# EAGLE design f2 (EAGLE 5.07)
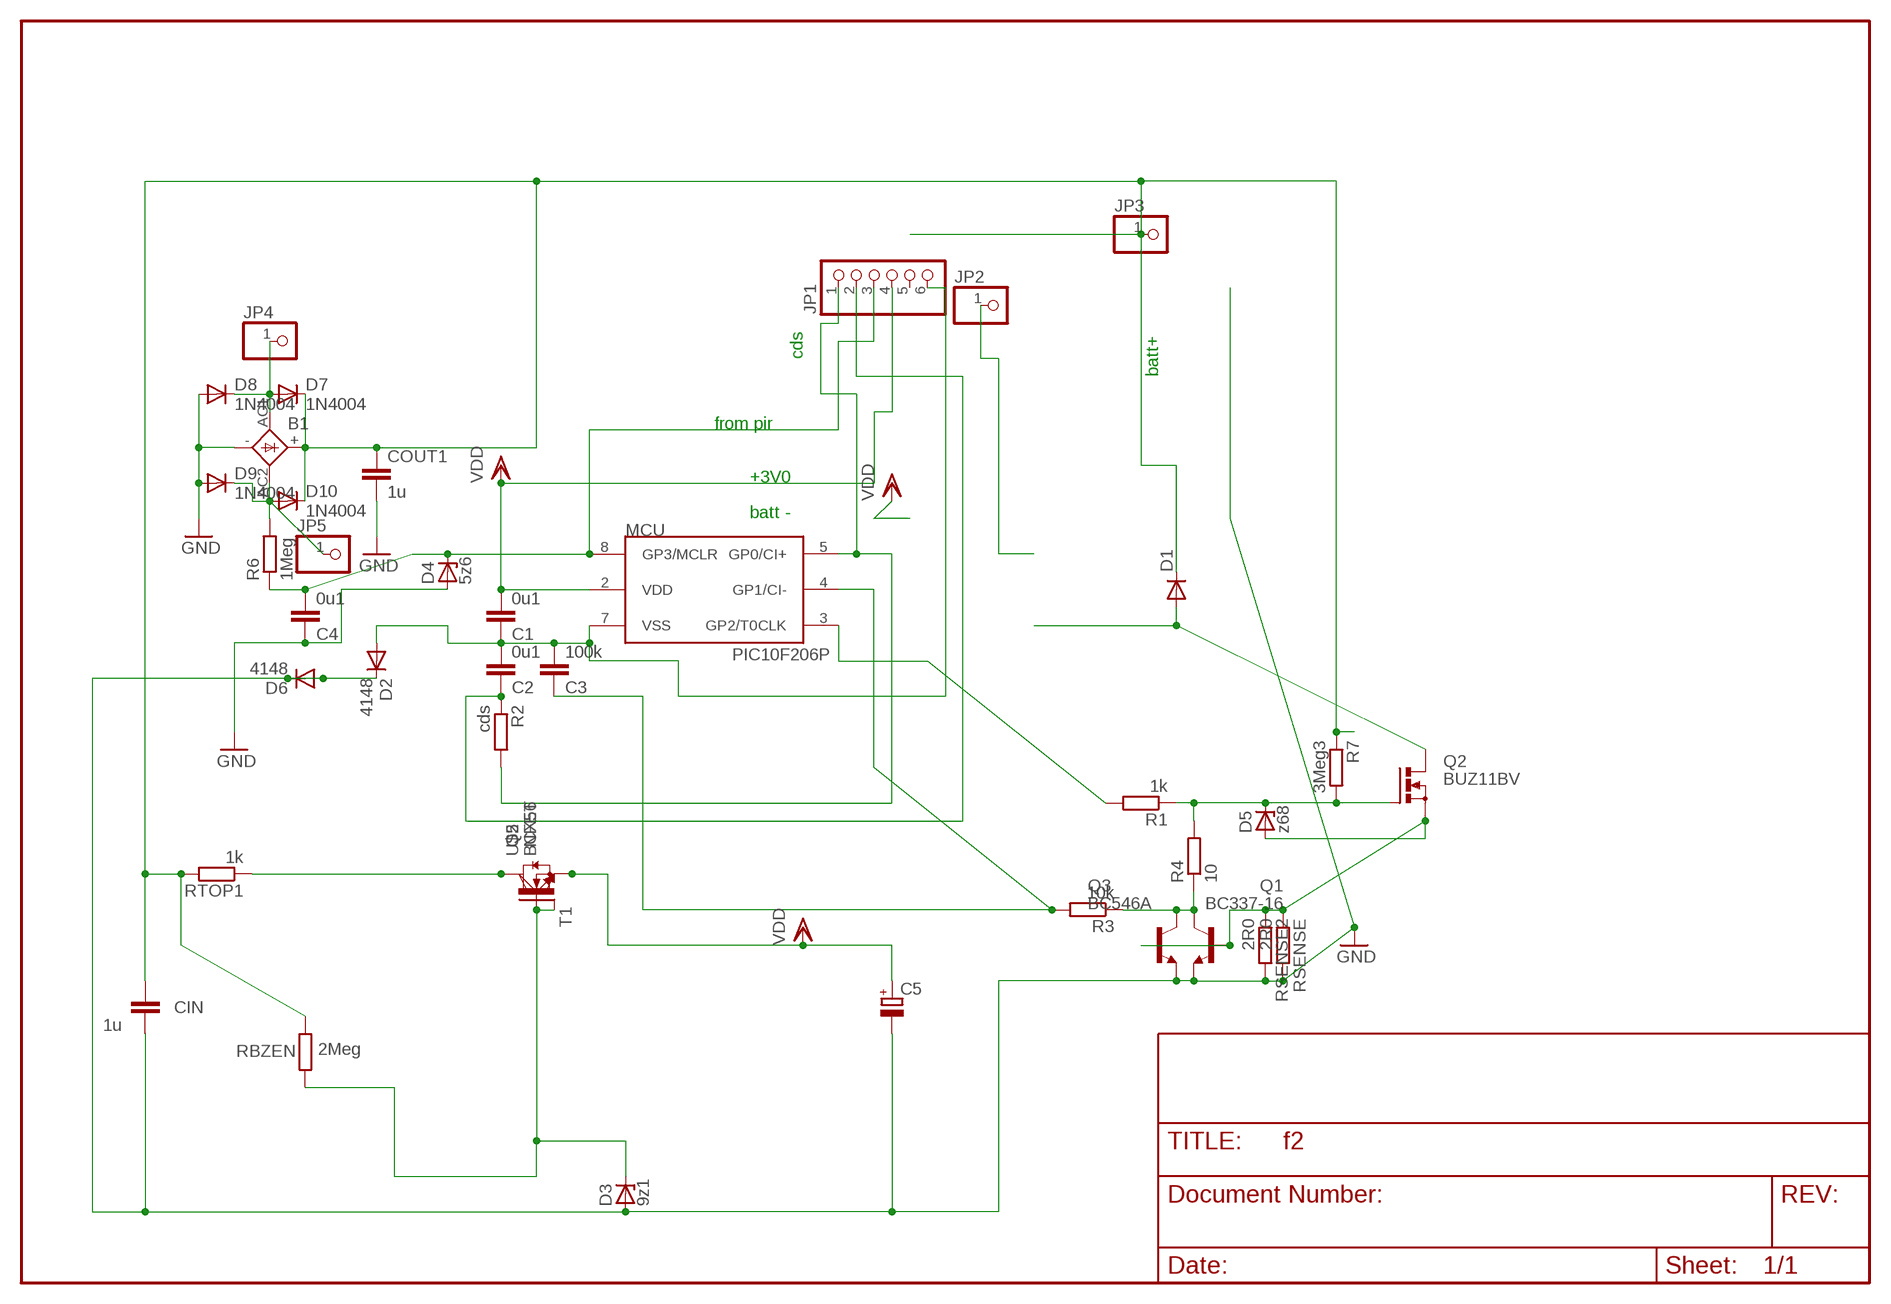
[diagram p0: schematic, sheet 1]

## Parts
B1  1KAB  [1KAB]
C1  0u1  C-EUC1206  [C1206]
C2  0u1  C-EUC0805  [C0805]
C3  100k  C-EUC1206  [C1206]
C4  0u1  C-EUC1206  [C1206]
C5  CPOL-EUSANYO_SMD_C6  [SANYO-OSCON_SMD_C6]
CIN  1u  C-EU050-024X044  [C050-024X044]
COUT1  1u  C-EU075-032X103  [C075-032X103]
D1  DIODE-SMC  [SMC]
D2  4148  1N4148MINIMELF  [MINIMELF]
D3  9z1  ZENER-DIODESOD80C  [SOD80C]
D4  5z6  ZENER-DIODESOD80C  [SOD80C]
D5  z68  ZENER-DIODEZD-5  [ZDIO-5]
D6  4148  1N4148MINIMELF  [MINIMELF]
D7  1N4004  [D-3.75]
D8  1N4004  [D-3.75]
D9  1N4004  [D-3.75]
D10  1N4004  [D-3.75]
JP1  PINHD-1X6  [1X06BOX]
JP2  PINHD-1X11X0.4  [1X01]
JP3  PINHD-1X11X0.4  [1X01]
JP4  PINHD-1X11X0.4  [1X01]
JP5  PINHD-1X11X0.4  [1X01]
MCU  PIC10F206P  [DIL8]
Q1  BC337-16  [TO92]
Q2  BUZ11BV  [TO220BV]
Q3  BC546A  [TO92-EBC]
Q5  NFET  N-HEXFET_DPAK-  [TO252]
R1  1k  R-EU_R0805  [R0805]
R2  cds  R-EU_0204/2V  [0204V]
R3  10k  R-EU_R1206  [R1206]
R4  10  R-EU_0207/3V  [0207/3V]
R6  1Meg  R-EU_0207/30  [0207/30]
R7  3Meg3  R-EU_0207/3V  [0207/3V]
RBZEN  2Meg  R-EU_0204/7  [0204/7]
RSENSE  2R0  R-EU_0207/3V  [0207/3V]
RSENSE2  2R0  R-EU_0207/3V  [0207/3V]
RTOP1  1k  R-EU_R1206  [R1206]
T1  -NPN-TO126V  [TO126V]
U$2  BCX56  [SOT223]

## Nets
AC1: B1.AC1 D7.A D8.C JP4.1
AC2: B1.AC2 D9.C D10.A JP5.1 R6.2
BN: D5.A Q1.2(B) Q2.S Q3.B RSENSE2.1 RSENSE.1
C: Q5.3(D) RTOP1.1 T1.2(C) U$2.2(C)
CB: D3.C Q5.1(G) RBZEN.2 T1.3(B) U$2.1(B)
CN: Q1.3(C) Q3.C R3.1 R4.1
GATE: D5.C Q2.G R1.1 R4.2 R7.2
GND: B1.- C4.1 C5.- CIN.2 COUT1.2 D2.C D3.A D4.A D6.A D6.C D8.A D9.A Q1.1(E) Q3.E RSENSE2.2 RSENSE.2
HOT: D1.A Q2.D
LED-: JP2.1
N$2: JP1.1 MCU.5(GP0/CI+) R2.2
N$4: C3.1 MCU.4(GP1/CI-) R3.2
N$6: C4.2 D4.C JP1.3 MCU.8(GP3/MCLR) R6.1
N$11: C2.1 JP1.2 R2.1
N$14: MCU.3(GP2/T0CLK) R1.2
VDD: C1.2 C5.+ JP1.4 MCU.2(VDD) Q5.2(S) T1.1(E) U$2.3(E)
VPLUS: B1.+ CIN.1 COUT1.1 D1.C D7.C D10.C JP3.1 R7.1 RBZEN.1 RTOP1.2
VSS: C1.1 C2.2 C3.2 D2.A JP1.6 MCU.7(VSS)
Unconnected: JP1.5

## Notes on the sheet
- cds
- batt+
- from pir
- +3V0
- batt -

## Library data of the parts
B1 = rectifier:1KAB: RECTIFIER grid 5,08 x 5,08 mm
C1-C4 CIN COUT1 = rcl:C-EU: CAPACITOR, European symbol
C5 = rcl-2:CPOL-EU: POLARIZED CAPACITOR, European symbol
D1 = diode-1:DIODE-: DIODE
D2 D6 = diode-1:1N4148: DIODE
D3-D5 = diode:ZENER-DIODE: Z-Diode
D7-D10 = diode:1N4004: DIODE
JP1 = pinhead:PINHD-1X6: PIN HEADER
JP2-JP5 = pinhead:PINHD-1X1: PIN HEADER
MCU = microchip-3:PIC10F2*: uPC nW 0,25/0,5k Program Flash memory Comparator
Q1 = transistor-npn:BC337*: NPN Transistor
Q2 = transistor-power:BUZ11: N-CHANNEL MOS FET
Q3 = transistor-npn:BC546*: NPN Transistor
Q5 = transistor-power:N-HEXFET_?-*: HEXFET® Power MOSFET
R1-R4 R7 RBZEN RSENSE RSENSE2 RTOP1 = rcl:R-EU_: RESISTOR, European symbol
R6 = rcl-2:R-EU_: RESISTOR, European symbol
T1 = transistor:*-NPN-: NPN Transistror BF959 corrected 2008.03.06
U$2 = transistor-power:BCX56

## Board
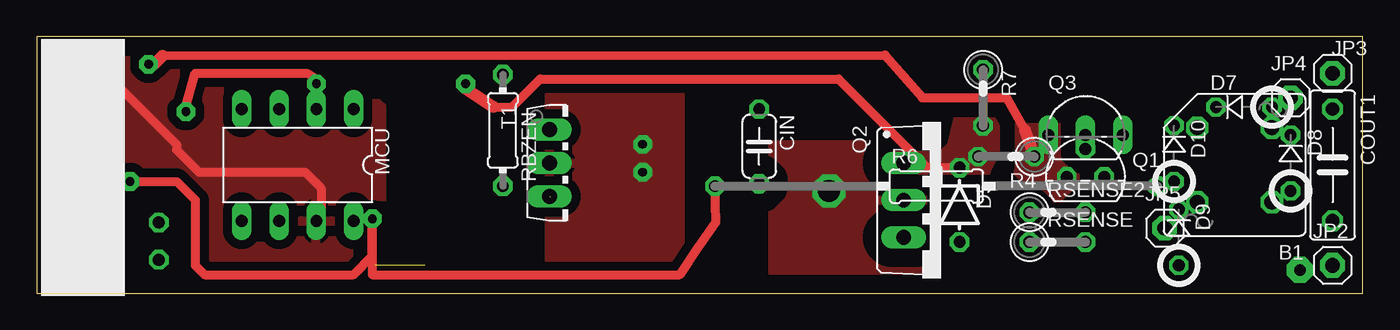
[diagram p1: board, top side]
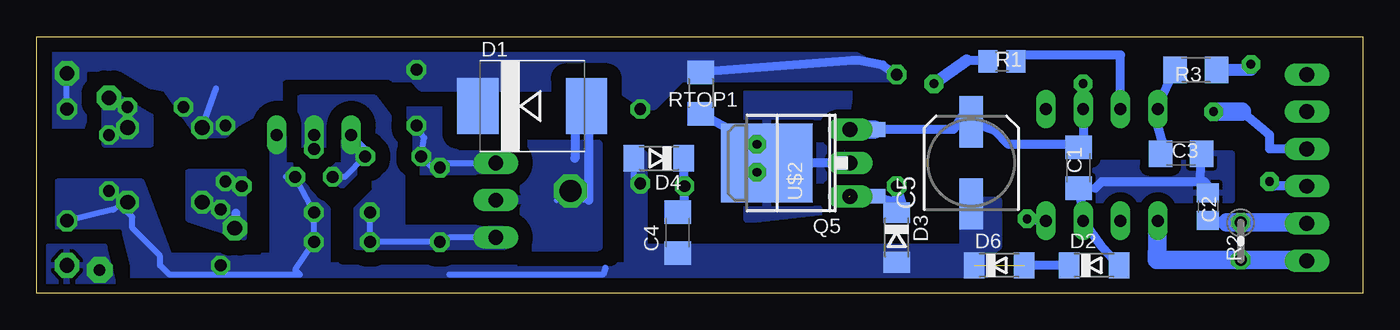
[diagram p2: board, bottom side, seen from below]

Size 90.33 x 17.5 mm. Coordinates in mm from the lower left corner, seen from the top.
Outline: 0,0 90.33,0 90.33,17.5 0,17.5 0,0
Copper layers (1*16): Top 0.035mm / dielectric 1.5mm / Bottom 0.035mm
Design rules "default *": minimum track width 10mil, minimum drill 24mil, track to track 8mil, track to pad 8mil, pad to pad 8mil, via to via 8mil, smd to smd 8mil, copper to edge 20mil, drill to drill 8mil, minimum pad ring 10mil, minimum via ring 8mil, stop-mask expansion 4mil, vias tented up to drill 0mil, thermal gap 10mil

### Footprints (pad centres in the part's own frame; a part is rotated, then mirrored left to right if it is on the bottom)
1KAB = drill 1.016 octagon: + 2.54,-2.54; - -2.54,2.54; AC1 -2.54,-2.54; AC2 2.54,2.54
C1206 = smd 1.6 x 1.8: 1 -1.4,0; 2 1.4,0
C0805 = smd 1.3 x 1.5: 1 -0.95,0; 2 0.95,0
SANYO-OSCON_SMD_C6 = smd 3.5 x 1.6: + 2.8,0; - -2.8,0
C050-024X044 = drill 0.813 octagon: 1 -2.54,0; 2 2.54,0
C075-032X103 = drill 0.914 octagon: 1 -3.81,0; 2 3.81,0
SMC = smd 2.8 x 3.8: A 3.7,0; C -3.7,0
MINIMELF = smd 1.4 x 1.8: A 1.7,0; C -1.7,0
SOD80C = smd 1.4 x 1.8: A 1.7,0; C -1.7,0
ZDIO-5 = drill 0.813 octagon: A 2.54,0; C -2.54,0
D-3.75 = drill 0.8 octagon: A 2.54,0; C -1.27,0
1X06BOX = drill 1.016 long: 1 -6.35,0; 2 -3.81,0; 3 -1.27,0; 4 1.27,0; 5 3.81,0; 6 6.35,0
1X01 = drill 1 pad 1.676 octagon: 1 0,0
DIL8 = drill 0.813 long: 1 -3.81,-3.81; 2 -1.27,-3.81; 3 1.27,-3.81; 4 3.81,-3.81; 5 3.81,3.81; 6 1.27,3.81; 7 -1.27,3.81; 8 -3.81,3.81
TO92 = drill 0.813 octagon: 1 1.27,0; 2 0,1.905; 3 -1.27,0
TO220BV = drill 1.016 long: D 0,-2.54; G -2.54,-2.54; S 2.54,-2.54
TO92-EBC = drill 0.813 long: B 0,-1.27; C -2.54,-1.27; E 2.54,-1.27
TO252 = smd 1 x 1.6: 1 -2.28,-3.53; 2 2.28,-3.53 | smd 5.4 x 6.2: 3 0,3.77
R0805 = smd 1.3 x 1.5: 1 -0.95,0; 2 0.95,0
0204V = drill 0.813 octagon: 1 -1.27,0; 2 1.27,0
R1206 = smd 1.6 x 1.803: 1 -1.422,0; 2 1.422,0
0207/3V = drill 0.813 octagon: 1 -1.27,0; 2 2.54,0
0207/30 = drill 0.813 octagon: 1 -15.08,0; 2 15.08,0
0204/7 = drill 0.813 octagon: 1 -3.81,0; 2 3.81,0
TO126V = drill 1.016 long: 1 -2.286,-1.27; 2 0,-1.27; 3 2.286,-1.27
SOT223 = smd 1.219 x 2.235: 1 -2.311,-3.099; 2 0,-3.099; 3 2.311,-3.099 | smd 3.6 x 2.2: 4 0,3.099

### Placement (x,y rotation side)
B1  81.6,8.75 180 top
C1  19.37,8.57 90 bottom
C2  10.54,5.91 90 bottom
C3  12.38,9.53 0 bottom
C4  46.67,4.13 90 bottom
C5  26.67,8.89 90 bottom
CIN  49.21,10.02 270 top
COUT1  88.27,8.75 270 top
D1  56.58,12.76 0 bottom
D2  18.3,1.91 0 bottom
D3  31.75,3.81 270 bottom
D4  47.94,9.21 180 bottom
D5  62.87,6.03 270 top
D6  24.77,1.91 0 bottom
D7  81.6,12.7 0 top
D8  85.41,9.53 270 top
D9  77.79,4.45 270 top
D10  77.47,10.16 270 top
JP1  3.81,8.57 90 top
JP2  88.27,1.91 0 top
JP3  88.27,15 0 top
JP4  85.41,13.34 0 top
JP5  76.83,4.45 0 top
MCU  17.78,8.75 180 top
Q1  71.44,7.94 0 top
Q2  61.59,6.35 270 top
Q3  71.44,12.06 0 top
Q5  36.83,8.89 90 bottom
R1  24.57,15.81 0 bottom
R2  8.32,3.56 270 bottom
R3  11.37,15.24 180 bottom
R4  66.67,9.32 180 top
R6  61.28,7.3 0 top
R7  64.45,13.97 270 top
RBZEN  31.75,11.11 270 top
RSENSE  68.9,3.49 0 top
RSENSE2  68.9,5.53 0 top
RTOP1  45.09,13.65 90 bottom
T1  36.2,8.89 270 top
U$2  38.1,8.89 90 bottom

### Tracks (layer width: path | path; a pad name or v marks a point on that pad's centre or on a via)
AC1
  Bottom 0.406: D8.C B1.AC1
  pour Bottom (isolate 0.61, no thermals): 82.55,12.06 85.72,13.97 85.72,10.16 82.55,10.16
AC2
  Bottom 0.406: R6.2 D10.A
  Bottom 0.61: JP5.1 76.75,5.48
  pour Bottom (isolate 0.813, rank 2, no thermals): 76.2,3.81 76.2,8.26 80.01,8.26 80.01,5.08
BN
  Bottom 0.406: Q2.S 62.23,3.81 D5.A RSENSE.1 RSENSE2.1
  pour Bottom (isolate 1.016, no thermals): 58.42,4.45 65.41,4.45 65.41,10.79 67.31,13.34 72.39,13.34 72.39,10.16 67.31,10.16 67.31,6.99 68.58,5.71 68.58,3.17 58.42,3.17
C  (via drill 0.6 pad 1.27)
  Bottom 0.406: T1.2 U$2.2 | v41.27,10.16 40.64,10.16 40.64,9.53
  Bottom 0.61: 40.01,8.89 40.64,9.53 | U$2.2 39.37,8.89 | 39.37,8.89 40.01,8.89 | RTOP1.1 43.33,11.28 42.55,9.53 39.37,8.89 | 40.01,8.89 Q5.3
  other vias: 41.27,8.26
  pour Bottom (isolate 0.61, rank 5): 34.92,13.97 41.91,13.97 41.91,5.08 36.2,5.71
  pour Top (isolate 0.61, rank 4): 34.92,13.97 43.81,13.97 43.81,1.91 34.92,1.91
CB  (1 unrouted)
  Bottom 0.61: D3.C RBZEN.2 31.39,6.07 Q5.1 34.29,6.61
  Bottom 1.27: 34.29,6.61 T1.3
CN  (via drill 0.6 pad 1.27)
  Top 0.61: 67.31,11.11 66.04,13.34 60.33,13.34 57.78,16.25 8.57,16.19 | v7.62,15.62 8,15.62
  Top 0.813: 8,15.62 8.57,16.19 | 67.31,11.11 R4.1
  Bottom 0.406: Q1.3 69.33,7.94 R4.1 67.94,9.84 Q3.C
  Bottom 0.61: 7.62,15.24 v7.62,15.62
  Bottom 0.813: R3.1 7.62,15.24
  pour Bottom (isolate 1.016, rank 5, no thermals): 68.58,11.43 69.85,11.43 69.85,9.53 71.12,8.26 71.12,7.62 69.85,6.35 68.58,6.35 66.67,8.26 66.67,11.43
  pour Top (isolate 1.016, rank 5, no thermals): 68.58,11.43 69.85,11.43 69.85,9.53 71.12,8.26 71.12,7.62 69.85,6.35 68.58,6.35 66.67,8.26 66.67,11.43
GATE  (via drill 0.6 pad 1.27)
  Top 0.61: v29.21,14.29 29.21,13.97 | 31.11,12.7 32.38,12.7 34.29,14.61 54.61,14.61 60.64,8.57 D5.C
  Top 0.813: 29.21,13.97 31.11,12.7
  Bottom 0.406: R7.2 63.94,10.6 R4.2 63.38,8.57 D5.C 62.55,8.89 Q2.G
  Bottom 0.61: 26.99,15.88 26.22,15.88 R1.1
  Bottom 0.813: 26.99,15.88 v29.21,14.29
  pour Bottom (isolate 1.016, rank 4, no thermals): 62.87,12.7 65.41,12.7 66.04,12.06 66.04,9.53 64.77,8.26 58.42,8.26 58.42,9.53 61.59,9.53 62.23,10.16
  pour Top (isolate 1.016, rank 4, no thermals): 62.87,12.7 65.41,12.7 65.41,9.53 64.77,8.26 58.42,8.26 58.42,9.53 61.59,9.53 62.23,10.16
GND  (1 unrouted)
  Bottom 0.406: COUT1.2 85.09,5.71 84.59,5.97 | 84.59,5.97 B1.- | 62.23,1.27 51.75,1.27 51.58,1.76 | CIN.2 49.64,7.48 D4.A | 84.59,5.97 83.82,5.21 83.82,4.45 81.92,2.54 81.92,1.91 81.28,1.27 72.39,1.27 72.71,1.59 RSENSE.2 RSENSE2.2 Q1.1 73.34,7.94
  Bottom 0.61: D2.C D6.A
  pour Bottom (isolate 1.016, rank 4, no thermals): 83.19,7.62 88.9,7.62 88.9,3.81 86.36,3.81 83.19,0 25.72,0 25.72,2.54 24.77,3.17 24.77,6.35 27.3,6.35 27.3,3.17 48.9,3.17 48.9,9.53 50.16,9.53 50.16,1.91 70.48,1.91 70.48,5.71 73.03,8.26 73.03,11.43 74.3,11.43 74.3,2.54 81.28,2.54
HOT  (via drill 1.5 pad 1.27)
  Bottom 0.406: D1.A 52.7,12.13 52.7,11.43 | 52.7,6.35 54.91,6.35
  Bottom 0.61: 52.7,6.35 52.7,11.43 53.34,11.43 53.66,11.11 53.66,9.21
  other vias: 53.98,6.99
  pour Bottom (isolate 1.016): 52.07,10.16 57.15,10.16 59.05,8.26 59.69,8.26 59.69,3.17 52.07,3.17
  pour Top (isolate 1.27): 50.16,10.16 57.15,10.16 59.05,8.26 60.33,8.26 60.33,1.27 50.16,1.27
LED-  (via drill 0.8 pad 1.78)
  other vias: 86.04,1.59
  pour Bottom (isolate 0.61, rank 3): 85.72,3.17 89.53,3.17 89.53,0.64 85.09,0.64
N$2
  Bottom 0.406: JP1.1 4.06,2.29
  Bottom 1.27: 4.06,2.29 R2.2 14.03,2.29 MCU.5
N$4
  Bottom 0.406: MCU.4 13.97,12.79 | C3.1 13.65,10.35
  Bottom 0.61: 13.97,12.79 R3.2 | MCU.4 13.97,11.43 13.65,10.35
N$6  (via drill 0.6 pad 1.27)
  Top 0.61: R6.1 46.26,4.86 45.09,3.17 43.81,1.27 22.86,1.27 v22.86,5.08 22.86,2.54 21.59,1.27 11.43,1.27 10.79,1.91 10.79,6.35 9.53,7.62 v6.35,7.62
  Bottom 0.406: 46.26,5.53 C4.2 | 46.26,9.21 D4.C
  Bottom 0.61: MCU.8 21.73,4.94 v22.86,5.08 | JP1.3 6.03,7.3 v6.35,7.62 | 46.26,5.53 R6.1 46.26,9.21
N$11
  Bottom 0.406: 9.27,4.83 C2.1 | JP1.2 4.06,4.83
  Bottom 1.27: 9.27,4.83 R2.1 4.06,4.83
N$14
  Bottom 0.406: 22.86,16.25 23.56,15.81 R1.2
  Bottom 0.61: MCU.3 16.51,16.25 22.86,16.25
VDD  (via drill 0.6 pad 1.27)
  Top 0.61: v10.16,12.38 10.16,12.7 10.79,15 18.41,15 19.05,14.61 v19.05,14.29 | MCU.2 19.05,12.7
  Bottom 0.406: MCU.2 19.05,12.7 | 19.05,10.29 C1.2 | T1.1 34.34,11.18 U$2.3
  Bottom 0.61: 19.05,10.29 MCU.2 v19.05,14.29 | JP1.4 6.35,9.84 6.35,10.79 8.26,12.38 | Q5.2 27.88,11.17 27.3,12.06 26.67,12.06 C5.+ 25.06,11.09 24.13,10.16 19.55,10.16 C1.2
  Bottom 1.27: 8.26,12.38 v10.16,12.38 | Q5.2 34.28,11.17 T1.1
VPLUS
  Bottom 0.406: B1.+ 78.11,13.97 | COUT1.1 JP3.1
  Bottom 0.61: RBZEN.1 32.7,15.56 34.29,15.88 34.77,15.88 RTOP1.2
  pour Bottom (isolate 1.016, rank 3, no thermals): 89.53,11.43 87,11.43 87,14.61 85.09,14.61 81.6,13.97 79.38,10.79 77.47,10.79 76.83,11.43 72.39,13.97 71.75,14.61 64.77,14.61 64.14,13.97 50.8,13.97 48.9,12.7 48.26,12.7 46.35,14.61 31.43,14.61 34.92,16.51 89.53,17.14
VSS
  Top 0.61: JP1.6 4.76,14.92 9.53,10.16 9.53,9.78 11.04,8.27 18.27,8.27 C1.1 19.37,5.26 MCU.7
  Bottom 0.406: MCU.7 19.05,5.58 | C1.1 18.23,7.17 | 10.77,7.62 11.05,7.81
  Bottom 0.61: D2.A 17.78,3.17 MCU.7 | 19.05,5.58 C1.1 | 18.23,7.17 17.78,7.62 10.77,7.62 10.54,7.33 C2.2 | 11.05,7.81 C3.2
  pour Top (isolate 0.61): 3.17,15.88 20.32,15.88 23.5,12.7 23.5,2.54 22.86,1.91 3.17,1.91 3.17,2.54 3.17,12.06
  pour Bottom (isolate 0.61): 8.89,9.53 11.43,9.53 12.06,8.89 17.78,8.89 18.41,8.26 18.41,6.35 8.89,6.35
